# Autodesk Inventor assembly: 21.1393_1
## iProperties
Created: 2011-07
Part Number: 21.1393_1
Document SubType Name: Assembly
Designer: Administrator
Description: POWER-LOCK BODY WITH SET SCREW
Mass: 19.1837 g
Surface Area: 23.5938 cm^2
Volume: 2.44287 cm^3
Density: 7.85292 g/cm^3
Author: Administrator
